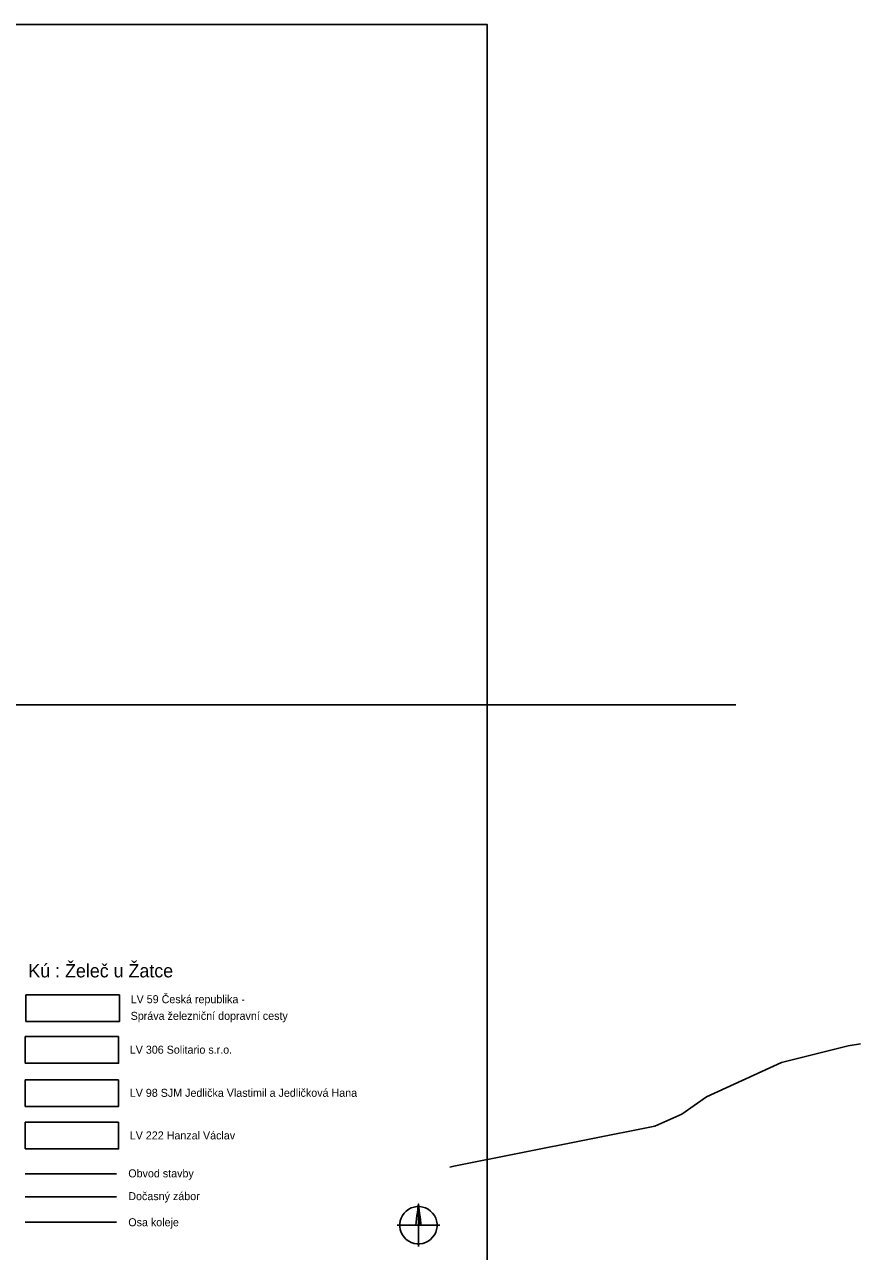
# Model space of a CAD drawing. Extents: x -801853 to -800578, y -1017479 to -1016338.
# Drawn here: x -800891.5 to -800578.3, y -1017204.8 to -1016745.1 of the extents above; entities that cross this region are included whole.
import ezdxf

# ---------------------------------------------------------------- set-up
doc = ezdxf.new("R2010")
doc.units = 0
for name, color, linetype in [('Default', 7, 'Continuous'), ('KLADY_ZMVM', 7, 'Continuous'), ('KN_HRANICE', 7, 'Continuous'), ('LEGENDA', 7, 'Continuous')]:
    doc.layers.add(name, color=color, linetype=linetype)

# ---------------------------------------------------------------- blocks, each defined once
blk = doc.blocks.new('SEVER')
at = {"layer": 'Default'}
for points in [[(5.5, 69.8), (16.3, 68.1), (26.7, 64.7), (36.5, 59.7), (45.4, 53.2), (53.2, 45.4), (59.7, 36.5), (64.7, 26.7), (68.1, 16.3), (69.8, 5.5), (69.8, -5.5), (68.1, -16.3), (64.7, -26.7), (59.7, -36.5), (53.2, -45.4), (45.4, -53.2), (36.5, -59.7), (26.7, -64.7), (16.3, -68.1), (5.5, -69.8), (-5.5, -69.8), (-16.3, -68.1), (-26.7, -64.7), (-36.5, -59.7), (-45.4, -53.2), (-53.2, -45.4), (-59.7, -36.5), (-64.7, -26.7), (-68.1, -16.3), (-69.8, -5.5), (-69.8, 5.5), (-68.1, 16.3), (-64.7, 26.7), (-59.7, 36.5), (-53.2, 45.4), (-45.4, 53.2), (-36.5, 59.7), (-26.7, 64.7), (-16.3, 68.1), (-5.5, 69.8), (5.5, 69.8)], [(-10, 0), (-8.5, 12), (-7, 24), (-5.5, 36), (-4, 48), (-2.5, 60), (-1, 72), (0, 80), (1.5, 68), (3, 56), (4.5, 44), (6, 32), (7.5, 20), (9, 8), (10, 0), (9.2, 0.8), (9.2, 5.6), (8.4, 12), (8.4, 0.8), (7.6, 0.8), (7.6, 13.5), (7.6, 18.4), (6.8, 24.8), (6.8, 12.1), (6.8, 0.8), (6, 0.8), (6, 13.5), (6, 26.2), (6, 31.2), (5.2, 36.8), (5.2, 24.1), (5.2, 11.4), (5.2, 0.8), (4.4, 0.8), (4.4, 13.5), (4.4, 26.2), (4.4, 38.9), (4.4, 43.2), (3.6, 50.4), (3.6, 37.7), (3.6, 25), (3.6, 12.3), (3.6, 0.8), (2.8, 0.8), (2.8, 13.5), (2.8, 26.2), (2.8, 38.9), (2.8, 51.6), (2.8, 56), (2, 63.2), (2, 50.5), (2, 37.8), (2, 25.1), (2, 12.4), (2, 0.8), (1.2, 0.8), (1.2, 13.5), (1.2, 26.2), (1.2, 38.9), (1.2, 51.6), (1.2, 64.3), (1.2, 69.6), (0.4, 76), (0.4, 63.3), (0.4, 50.6), (0.4, 37.9), (0.4, 25.2), (0.4, 12.5), (0.4, 0.8)], [(0, 80), (0, 67.3), (0, 54.6), (0, 41.9), (0, 29.2), (0, 16.5), (0, 3.8), (0, -8.9), (0, -21.6), (0, -34.3), (0, -47), (0, -59.7), (0, -72.4), (0, -80)], [(80, 0), (67.3, 0), (54.6, 0), (41.9, 0), (29.2, 0), (16.5, 0), (3.8, 0), (-8.9, 0), (-21.6, 0), (-34.3, 0), (-47, 0), (-59.7, 0), (-72.4, 0), (-80, 0)]]:
    blk.add_lwpolyline(points, dxfattribs=at)

msp = doc.modelspace()

# ---------------------------------------------------------------- linework, layer by layer
at = {"layer": 'KLADY_ZMVM'}
msp.add_line((-801848.02, -1017000), (-800625, -1017000), dxfattribs=at)
at = {"layer": 'KN_HRANICE'}
for p, q in [((-800607.87, -1017134.09), (-800582.96, -1017127.73)), ((-800582.96, -1017127.73), (-800578.33, -1017127)), ((-800636.06, -1017146.91), (-800607.87, -1017134.09)), ((-800645.22, -1017153.45), (-800636.06, -1017146.91)), ((-800730.67, -1017172.91), (-800655.34, -1017157.94)), ((-800655.34, -1017157.94), (-800645.22, -1017153.45)), ((-800732.16, -1017173.28), (-800730.67, -1017172.91))]:
    msp.add_line(p, q, dxfattribs=at)
at = {"layer": 'LEGENDA'}
for p, q in [((-800890.96, -1017108.71), (-800855.96, -1017108.71)), ((-800890.96, -1017108.71), (-800890.96, -1017118.71)), ((-800891.29, -1017124.32), (-800856.29, -1017124.32)), ((-800891.29, -1017124.32), (-800891.29, -1017134.32)), ((-800891.29, -1017140.48), (-800856.29, -1017140.48)), ((-800891.29, -1017140.48), (-800891.29, -1017150.48)), ((-800891.29, -1017156.44), (-800856.29, -1017156.44)), ((-800891.29, -1017156.44), (-800891.29, -1017166.44)), ((-800891.28, -1017175.82), (-800857.08, -1017175.82)), ((-800891.28, -1017184.37), (-800857.08, -1017184.37)), ((-800891.28, -1017193.82), (-800857.08, -1017193.82))]:
    msp.add_line(p, q, dxfattribs=at)
msp.add_lwpolyline([(-801559.16, -1017339.08), (-800718.16, -1017339.08), (-800718.16, -1016745.08), (-801559.16, -1016745.08)], close=True, dxfattribs=at)
for points in [[(-800855.96, -1017108.71), (-800855.96, -1017118.71), (-800890.96, -1017118.71)], [(-800856.29, -1017124.32), (-800856.29, -1017134.32), (-800891.29, -1017134.32)], [(-800856.29, -1017140.48), (-800856.29, -1017150.48), (-800891.29, -1017150.48)], [(-800856.29, -1017156.44), (-800856.29, -1017166.44), (-800891.29, -1017166.44)]]:
    msp.add_lwpolyline(points, dxfattribs=at)

# ---------------------------------------------------------------- block references
at = {"layer": 'LEGENDA', "xscale": 0.1, "yscale": 0.10000000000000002}
msp.add_blockref('SEVER', (-800743.94, -1017195.01), dxfattribs=at)

# ---------------------------------------------------------------- texts
at = {"layer": 'LEGENDA'}
for s, height, p in [('Kú : Želeč u Žatce', 5, (-800890.08, -1017102.15)), ('LV 59 Česká republika -', 3, (-800851.75, -1017111.82)), ('Správa železniční dopravní cesty', 3, (-800851.75, -1017118.06)), ('LV 306 Solitario s.r.o.', 3, (-800852.08, -1017130.74)), ('LV 98 SJM Jedlička Vlastimil a Jedličková Hana', 3, (-800852.08, -1017146.9)), ('LV 222 Hanzal Václav', 3, (-800852.08, -1017162.86)), ('Obvod stavby', 3, (-800852.63, -1017177.08)), ('Dočasný zábor', 3, (-800852.63, -1017185.62)), ('Osa koleje', 3, (-800852.63, -1017195.4))]:
    msp.add_text(s, height=height, dxfattribs=at).set_placement(p)

doc.saveas('drawing.dxf')
